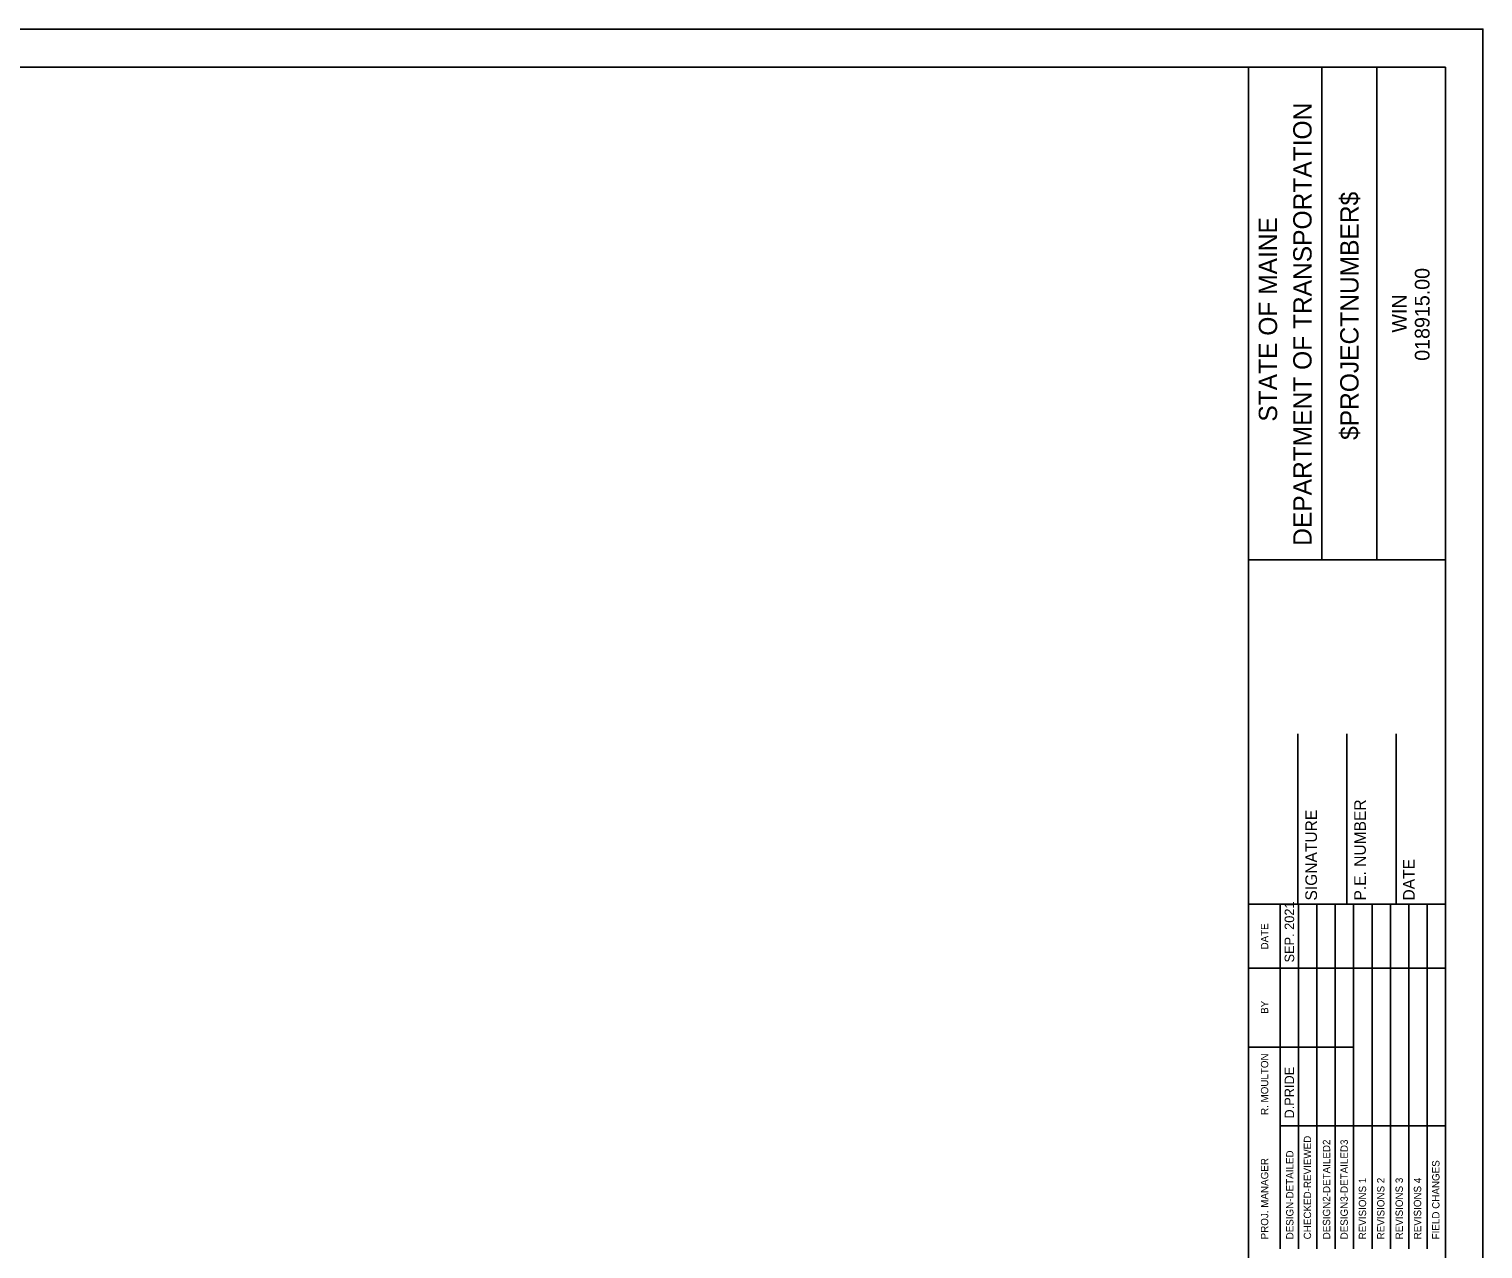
# Model space of a CAD drawing. Extents: x 844930 to 845273, y 363538 to 363758.
# Drawn here: x 845122 to 845269.7, y 363633.7 to 363757.6 of the extents above; entities that cross this region are included whole.
import ezdxf

# ---------------------------------------------------------------- set-up
doc = ezdxf.new("R2010")
doc.units = 0
doc.layers.add('BORDER', color=7, linetype='Continuous')
doc.layers.add('PLOT BOUNDARY', color=7, linetype='Continuous')

msp = doc.modelspace()

# ---------------------------------------------------------------- linework, layer by layer
at = {"layer": 'BORDER'}
for p, q in [((845245.88, 363543.72), (845245.88, 363753.72)), ((845253.33, 363703.72), (845253.33, 363753.72)), ((845258.92, 363703.72), (845258.92, 363753.72)), ((845245.88, 363703.71), (845265.88, 363703.71)), ((845250.88, 363668.73), (845250.88, 363686.02)), ((845255.88, 363668.73), (845255.88, 363686.02)), ((845260.88, 363668.73), (845260.88, 363686.02)), ((845245.88, 363668.73), (845265.88, 363668.73))]:
    msp.add_line(p, q, dxfattribs=at)
msp.add_lwpolyline([(844945.88, 363543.72), (845265.88, 363543.72), (845265.88, 363753.72), (844945.88, 363753.72)], close=True, dxfattribs=at)
for points in [[(845249.11, 363662.23), (845249.11, 363668.73)], [(845250.97, 363633.73), (845250.97, 363668.73)], [(845252.83, 363668.73), (845252.83, 363633.73)], [(845254.7, 363633.73), (845254.7, 363668.73)], [(845256.56, 363633.73), (845256.56, 363668.73)], [(845258.43, 363633.73), (845258.43, 363668.73)], [(845260.29, 363633.73), (845260.29, 363668.73)], [(845262.15, 363633.73), (845262.15, 363668.73)], [(845264.02, 363633.73), (845264.02, 363668.73)], [(845249.11, 363633.73), (845249.11, 363667.31)], [(845245.88, 363662.23), (845265.88, 363662.23)], [(845245.88, 363654.23), (845249.11, 363654.23)], [(845249.11, 363654.23), (845256.56, 363654.23)], [(845249.11, 363646.23), (845265.88, 363646.23)]]:
    msp.add_lwpolyline(points, dxfattribs=at)
at = {"layer": 'PLOT BOUNDARY'}
msp.add_lwpolyline([(844929.69, 363537.6), (845269.69, 363537.6), (845269.69, 363757.6), (844929.69, 363757.6)], close=True, dxfattribs=at)

# ---------------------------------------------------------------- texts
at = {"layer": 'BORDER'}
for s, height, p in [('DEPARTMENT OF TRANSPORTATION', 1.8635, (845252.29, 363705.13)), ('$PROJECTNUMBER$', 1.8635, (845257.06, 363715.88)), ('STATE OF MAINE', 1.8635, (845248.79, 363717.74)), ('018915.00', 1.491, (845264.27, 363723.92)), ('WIN', 1.491, (845261.95, 363726.78)), ('P.E. NUMBER', 1.1811, (845257.8, 363669.11)), ('SIGNATURE', 1.181, (845252.84, 363669.11)), ('DATE', 1.181, (845262.76, 363669.11)), ('SEP. 2021', 0.969, (845250.52, 363662.82)), ('DATE', 0.743, (845247.89, 363664.14)), ('BY', 0.743, (845247.89, 363657.6)), ('R. MOULTON', 0.745, (845247.89, 363647.33)), ('D.PRIDE', 0.969, (845250.52, 363646.97)), ('CHECKED-REVIEWED', 0.7455, (845252.24, 363634.7)), ('DESIGN-DETAILED', 0.7455, (845250.45, 363634.7)), ('DESIGN2-DETAILED2', 0.7455, (845254.18, 363634.7)), ('DESIGN3-DETAILED3', 0.7455, (845255.97, 363634.7)), ('PROJ. MANAGER', 0.7455, (845247.89, 363634.7)), ('FIELD CHANGES', 0.7455, (845265.28, 363634.7)), ('REVISIONS 1', 0.7455, (845257.83, 363634.7)), ('REVISIONS 2', 0.7455, (845259.69, 363634.7)), ('REVISIONS 3', 0.7455, (845261.56, 363634.7)), ('REVISIONS 4', 0.7455, (845263.42, 363634.7))]:
    msp.add_text(s, height=height, rotation=90, dxfattribs=at).set_placement(p)

doc.saveas('drawing.dxf')
